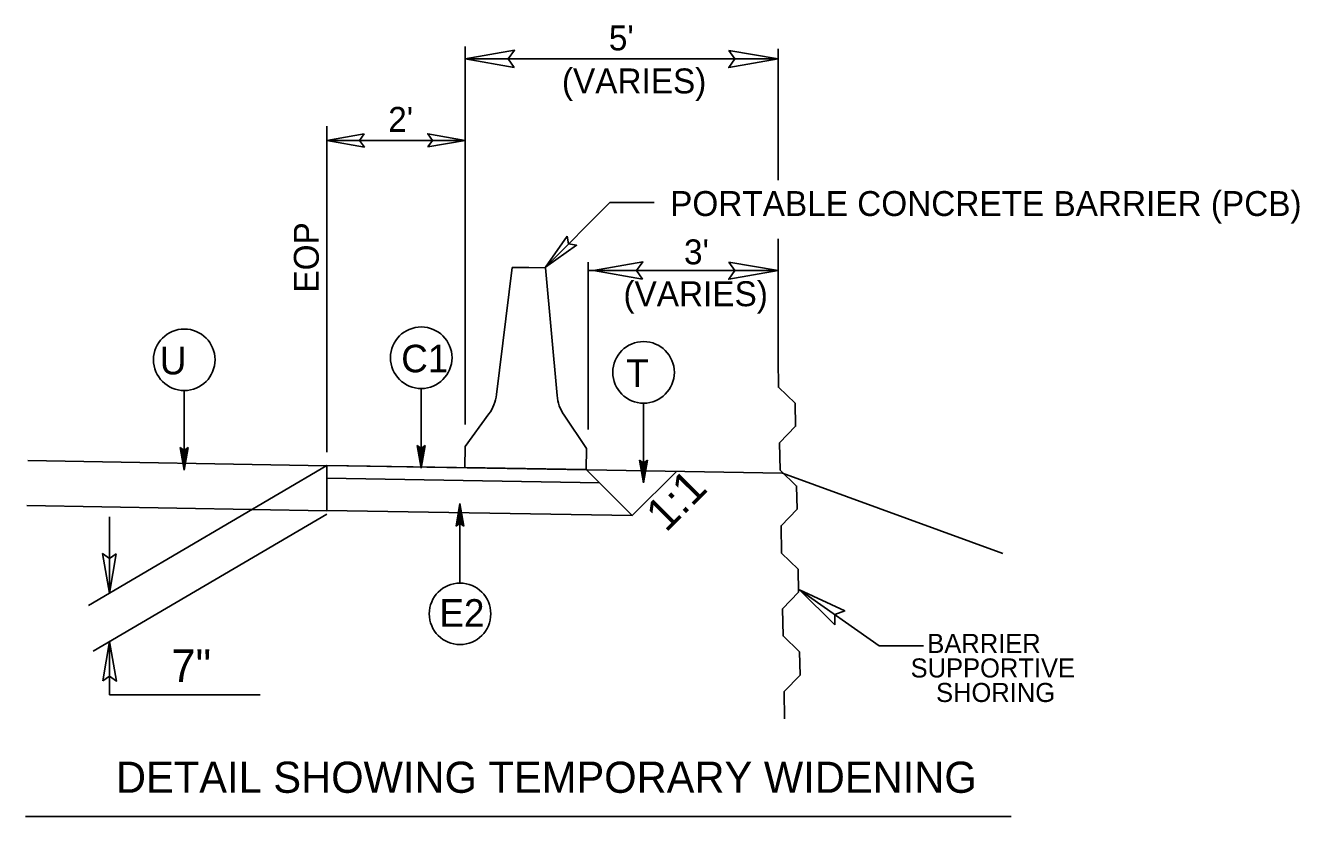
# Model space of a CAD drawing. Extents: x 981824 to 982276, y 44828 to 45204.
# Drawn here: x 982246.78 to 982276, y 45157.07 to 45175.21 of the extents above; entities that cross this region are included whole.
import ezdxf

# ---------------------------------------------------------------- set-up
doc = ezdxf.new("R2010")
doc.units = 0
for name, color, linetype in [('Old_Level_1', 7, 'Continuous'), ('Old_Level_2', 7, 'Continuous'), ('Old_Level_20', 7, 'Continuous'), ('Old_Level_3', 7, 'Continuous'), ('Old_Level_31', 7, 'Continuous'), ('Prop Terminator CELL', 7, 'Continuous'), ('Typical Median Barrier CELL', 7, 'Continuous'), ('Typical Terminator CELL', 7, 'Continuous')]:
    doc.layers.add(name, color=color, linetype=linetype)

msp = doc.modelspace()

# ---------------------------------------------------------------- linework, layer by layer
at = {"layer": 'Old_Level_1'}
for p, q in [((982256.864, 45166.061), (982256.864, 45174.73)), ((982264.038, 45171.667), (982264.038, 45174.678)), ((982264.038, 45174.446), (982256.864, 45174.446)), ((982253.686, 45165.43), (982253.686, 45172.902)), ((982256.864, 45172.577), (982253.686, 45172.577)), ((982260.184, 45171.156), (982258.702, 45169.67)), ((982261.201, 45171.156), (982260.184, 45171.156)), ((982264.038, 45167.541), (982264.038, 45170.318)), ((982259.685, 45165.946), (982259.685, 45169.786)), ((982264.038, 45169.591), (982259.685, 45169.591)), ((982250.418, 45165.014), (982250.325, 45165.534)), ((982250.325, 45165.534), (982250.418, 45165.463)), ((982250.343, 45165.524), (982250.418, 45165.014)), ((982250.418, 45165.014), (982250.352, 45165.513)), ((982250.366, 45165.502), (982250.418, 45165.014)), ((982250.418, 45165.014), (982250.381, 45165.495)), ((982250.395, 45165.484), (982250.418, 45165.014)), ((982250.418, 45165.014), (982250.403, 45165.475)), ((982250.418, 45165.014), (982250.507, 45165.534)), ((982250.418, 45165.463), (982250.507, 45165.534)), ((982250.418, 45165.014), (982250.496, 45165.524)), ((982250.484, 45165.513), (982250.418, 45165.014)), ((982250.418, 45165.014), (982250.469, 45165.502)), ((982250.455, 45165.495), (982250.418, 45165.014)), ((982250.418, 45165.014), (982250.444, 45165.484)), ((982250.43, 45165.475), (982250.418, 45165.014)), ((982250.418, 45165.463), (982250.418, 45165.014)), ((982255.854, 45165.061), (982255.761, 45165.581)), ((982255.761, 45165.581), (982255.854, 45165.51)), ((982255.779, 45165.571), (982255.854, 45165.061)), ((982255.854, 45165.061), (982255.788, 45165.56)), ((982255.802, 45165.549), (982255.854, 45165.061)), ((982255.854, 45165.061), (982255.817, 45165.542)), ((982255.831, 45165.531), (982255.854, 45165.061)), ((982255.854, 45165.061), (982255.839, 45165.522)), ((982255.854, 45165.061), (982255.943, 45165.581)), ((982255.854, 45165.51), (982255.943, 45165.581)), ((982255.854, 45165.061), (982255.932, 45165.571)), ((982255.92, 45165.56), (982255.854, 45165.061)), ((982255.854, 45165.061), (982255.905, 45165.549)), ((982255.891, 45165.542), (982255.854, 45165.061)), ((982255.854, 45165.061), (982255.88, 45165.531)), ((982255.866, 45165.522), (982255.854, 45165.061)), ((982255.854, 45165.51), (982255.854, 45165.061)), ((982253.686, 45165.111), (982246.828, 45165.235)), ((982260.954, 45164.725), (982260.861, 45165.245)), ((982260.861, 45165.245), (982260.954, 45165.174)), ((982260.879, 45165.235), (982260.954, 45164.725)), ((982260.954, 45164.725), (982260.888, 45165.224)), ((982260.902, 45165.213), (982260.954, 45164.725)), ((982260.954, 45164.725), (982260.917, 45165.206)), ((982260.931, 45165.195), (982260.954, 45164.725)), ((982260.954, 45164.725), (982260.939, 45165.186)), ((982260.954, 45164.725), (982261.043, 45165.245)), ((982260.954, 45165.174), (982261.043, 45165.245)), ((982260.954, 45164.725), (982261.032, 45165.235)), ((982261.02, 45165.224), (982260.954, 45164.725)), ((982260.954, 45164.725), (982261.005, 45165.213)), ((982260.991, 45165.206), (982260.954, 45164.725)), ((982260.954, 45164.725), (982260.98, 45165.195)), ((982260.966, 45165.186), (982260.954, 45164.725)), ((982260.954, 45165.174), (982260.954, 45164.725)), ((982253.686, 45165.119), (982248.224, 45161.912)), ((982259.661, 45165.021), (982253.686, 45165.119)), ((982259.639, 45165.028), (982260.694, 45163.971)), ((982264.142, 45164.946), (982259.661, 45165.02)), ((982261.707, 45164.986), (982260.694, 45163.971)), ((982264.142, 45164.946), (982269.192, 45163.101)), ((982259.942, 45164.725), (982253.69, 45164.828)), ((982253.686, 45164.077), (982246.809, 45164.202)), ((982253.686, 45164.004), (982248.331, 45160.861)), ((982260.694, 45163.971), (982253.686, 45164.086)), ((982256.742, 45164.248), (982256.653, 45163.729)), ((982256.667, 45163.739), (982256.742, 45164.248)), ((982256.742, 45164.248), (982256.678, 45163.751)), ((982256.69, 45163.757), (982256.742, 45164.248)), ((982256.742, 45164.248), (982256.704, 45163.768)), ((982256.719, 45163.775), (982256.742, 45164.248)), ((982256.742, 45164.248), (982256.73, 45163.786)), ((982256.742, 45164.248), (982256.834, 45163.729)), ((982256.742, 45163.797), (982256.742, 45164.248)), ((982256.756, 45163.786), (982256.742, 45164.248)), ((982256.742, 45164.248), (982256.77, 45163.775)), ((982256.785, 45163.768), (982256.742, 45164.248)), ((982256.742, 45164.248), (982256.797, 45163.757)), ((982256.809, 45163.751), (982256.742, 45164.248)), ((982256.742, 45164.248), (982256.822, 45163.739)), ((982248.704, 45163.944), (982248.704, 45162.194)), ((982256.653, 45163.729), (982256.742, 45163.797)), ((982256.742, 45163.797), (982256.834, 45163.729)), ((982248.704, 45161.08), (982248.704, 45159.864)), ((982252.157, 45159.864), (982248.704, 45159.864))]:
    msp.add_line(p, q, dxfattribs=at)
for points in [[(982264.038, 45167.541), (982264.049, 45166.917), (982264.43, 45166.549), (982264.44, 45166.02), (982264.073, 45165.64), (982264.084, 45165.015), (982264.465, 45164.647), (982264.474, 45164.118), (982264.107, 45163.738), (982264.119, 45163.113), (982264.499, 45162.746), (982264.509, 45162.217), (982264.142, 45161.836), (982264.153, 45161.211), (982264.534, 45160.844), (982264.544, 45160.315), (982264.176, 45159.934), (982264.188, 45159.309)], [(982253.691, 45165.119), (982253.689, 45164.086)], [(982267.378, 45160.982), (982266.361, 45160.982), (982264.531, 45162.272)]]:
    msp.add_lwpolyline(points, dxfattribs=at)
msp.add_lwpolyline([(982253.686, 45165.119), (982259.639, 45165.028), (982259.942, 45164.725), (982253.69, 45164.828)], close=True, dxfattribs=at)
at = {"layer": 'Old_Level_2'}
for p, q in [((982250.418, 45166.842), (982250.418, 45165.014)), ((982255.854, 45166.889), (982255.854, 45165.061)), ((982260.954, 45166.553), (982260.954, 45164.725)), ((982256.742, 45162.421), (982256.742, 45164.248))]:
    msp.add_line(p, q, dxfattribs=at)
for centre in [(982250.418, 45167.545), (982255.854, 45167.592), (982260.954, 45167.256), (982256.744, 45161.718)]:
    msp.add_circle(centre, 0.706, dxfattribs=at)
at = {"layer": 'Old_Level_3'}
msp.add_line((982269.384, 45157.069), (982246.776, 45157.069), dxfattribs=at)
at = {"layer": 'Prop Terminator CELL'}
for points in [[(982257.989, 45174.252), (982256.864, 45174.446), (982257.995, 45174.646), (982257.851, 45174.446)], [(982262.913, 45174.64), (982264.038, 45174.446), (982262.907, 45174.246), (982263.051, 45174.446)], [(982260.932, 45169.397), (982259.807, 45169.591), (982260.939, 45169.791), (982260.795, 45169.591)], [(982262.913, 45169.785), (982264.038, 45169.591), (982262.907, 45169.391), (982263.051, 45169.591)], [(982265.339, 45161.466), (982264.531, 45162.272), (982265.571, 45161.784), (982265.338, 45161.703)]]:
    msp.add_lwpolyline(points, close=True, dxfattribs=at)
at = {"layer": 'Typical Median Barrier CELL'}
for p, q in [((982257.94, 45169.664), (982257.582, 45166.749)), ((982258.324, 45169.658), (982257.94, 45169.664)), ((982258.324, 45169.658), (982258.708, 45169.651)), ((982258.708, 45169.651), (982258.969, 45166.726)), ((982257.406, 45166.302), (982256.864, 45165.554)), ((982259.13, 45166.274), (982259.647, 45165.508)), ((982256.856, 45165.074), (982256.864, 45165.554)), ((982259.639, 45165.028), (982259.647, 45165.508)), ((982258.251, 45165.243), (982258.251, 45165.243)), ((982256.856, 45165.074), (982259.639, 45165.028))]:
    msp.add_line(p, q, dxfattribs=at)
for centre, start, end in [((982256.629, 45166.866), 324.052, 352.9929), ((982259.925, 45166.811), 185.1034, 214.0418)]:
    msp.add_arc(centre, 0.96, start, end, dxfattribs=at)
at = {"layer": 'Typical Terminator CELL'}
for points in [[(982254.544, 45172.725), (982253.686, 45172.577), (982254.549, 45172.425), (982254.439, 45172.577)], [(982256.006, 45172.43), (982256.864, 45172.577), (982256.002, 45172.73), (982256.111, 45172.577)], [(982259.204, 45170.381), (982258.702, 45169.67), (982259.419, 45170.172), (982259.234, 45170.202)], [(982248.859, 45163.094), (982248.704, 45162.194), (982248.544, 45163.099), (982248.704, 45162.984)], [(982248.549, 45160.18), (982248.704, 45161.08), (982248.864, 45160.175), (982248.704, 45160.29)]]:
    msp.add_lwpolyline(points, close=True, dxfattribs=at)

# ---------------------------------------------------------------- texts
at = {"layer": 'Old_Level_1'}
for s, height, p in [("5'", 0.5717, (982260.158, 45174.641)), ('(VARIES)', 0.5717, (982259.081, 45173.655)), ("2'", 0.5717, (982255.097, 45172.773)), ('PORTABLE CONCRETE BARRIER (PCB)', 0.57168, (982261.564, 45170.843)), ("3'", 0.5717, (982261.882, 45169.734)), ('(VARIES)', 0.5717, (982260.493, 45168.774)), ('7"', 0.75, (982250.12, 45160.153)), ('DETAIL SHOWING TEMPORARY WIDENING', 0.71446, (982248.851, 45157.613))]:
    msp.add_text(s, height=height, dxfattribs=at).set_placement(p)
for s, height, rotation, p in [('EOP', 0.5717, 90, (982253.504, 45169.086)), ('1:1', 0.75, 45.0775, (982261.47, 45163.569))]:
    msp.add_text(s, height=height, rotation=rotation, dxfattribs=at).set_placement(p)
at = {"layer": 'Old_Level_20'}
for s, p in [('U ', (982249.858, 45167.211)), ('C1', (982255.395, 45167.258)), ('T ', (982260.556, 45166.922)), ('E2', (982256.271, 45161.423))]:
    msp.add_text(s, height=0.6316, dxfattribs=at).set_placement(p)
at = {"layer": 'Old_Level_31'}
for s, p in [('BARRIER ', (982267.463, 45160.821)), ('SUPPORTIVE', (982267.08, 45160.258)), ('SHORING', (982267.664, 45159.696))]:
    msp.add_text(s, height=0.4375, rotation=359.9999, dxfattribs=at).set_placement(p)

doc.saveas('drawing.dxf')
